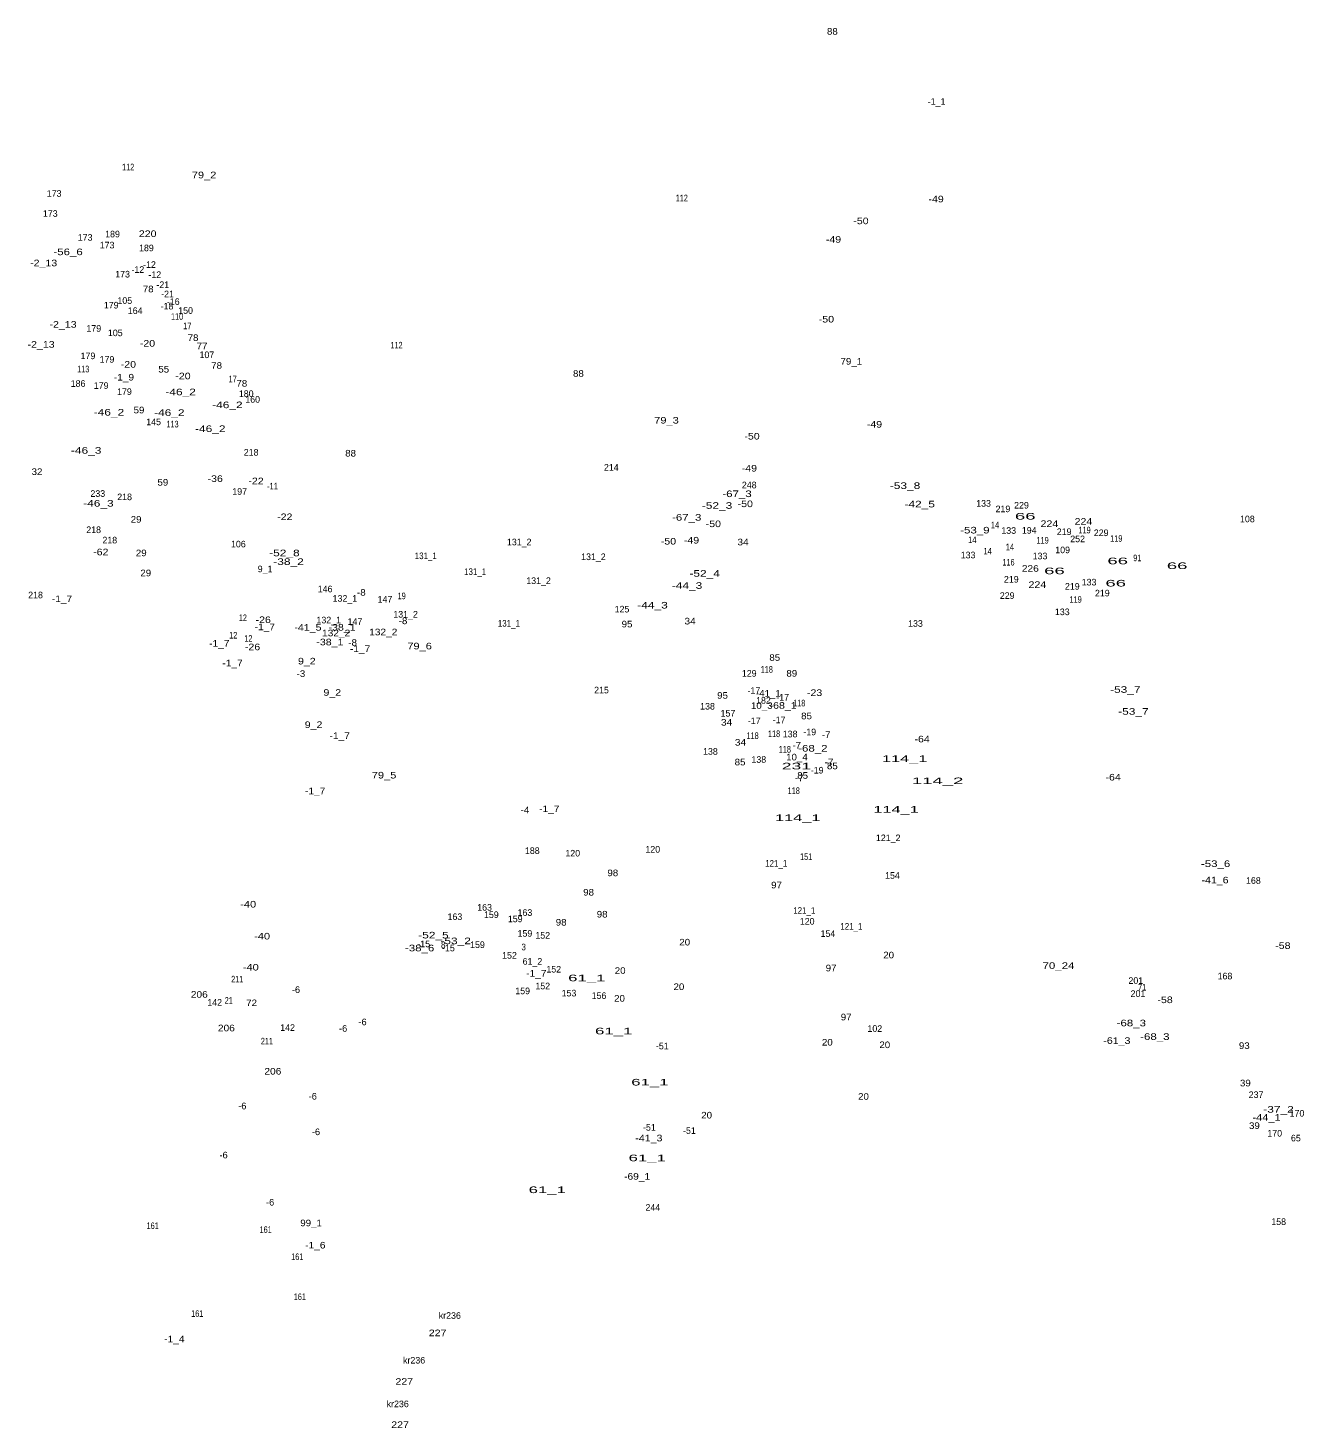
# Model space of a CAD drawing. Extents: x -659306 to -656317, y -989614 to -987663.
# Drawn here: x -657828 to -657055, y -988511 to -987663 of the extents above; entities that cross this region are included whole.
import ezdxf
from ezdxf.enums import TextEntityAlignment as Align

# ---------------------------------------------------------------- set-up
doc = ezdxf.new("R2010")
doc.units = 0
doc.header["$LTSCALE"] = 1.6
doc.layers.add('24', color=7, linetype='Continuous')

msp = doc.modelspace()

# ---------------------------------------------------------------- texts
at = {"layer": '24'}
for s, width, p in [('88', 1.1, (-657340.4, -987667.07)), ('112', 0.8, (-657767.06, -987749.26)), ('79_2', 1.25, (-657721.07, -987754.08)), ('112', 0.8, (-657431.63, -987768.04)), ('-49', 1.2, (-657277.551, -987768.69)), ('-50', 1.2, (-657323.08, -987781.9)), ('220', 1.2, (-657755.25, -987789.69)), ('-49', 1.2, (-657339.731, -987793.14)), ('-56_6', 1.3, (-657803.48, -987800.68)), ('-2_13', 1.2, (-657818.28, -987807.4)), ('78', 1.1, (-657754.94, -987823.18)), ('-2_13', 1.2, (-657806.53, -987844.61)), ('110', 0.8, (-657737.43, -987839.87)), ('-50', 1.2, (-657344.01, -987841.48)), ('17', 0.85, (-657731.221, -987845.54)), ('78', 1.1, (-657727.77, -987852.71)), ('-2_13', 1.2, (-657819.84, -987856.76)), ('-20', 1.2, (-657755.4, -987856.13)), ('77', 1.1, (-657722.341, -987857.75)), ('112', 0.8, (-657604.48, -987857.23)), ('-20', 1.2, (-657766.95, -987868.86)), ('78', 1.1, (-657713.49, -987869.53)), ('79_1', 1.1, (-657328.91, -987867.01)), ('113', 0.8, (-657794.3, -987871.68)), ('-1_9', 1.15, (-657769.671, -987876.65)), ('55', 1.1, (-657745.52, -987871.81)), ('-20', 1.2, (-657733.87, -987875.91)), ('17', 0.85, (-657703.74, -987877.7)), ('88', 1.1, (-657494.27, -987874.4)), ('-46_2', 1.35, (-657735.3, -987885.57)), ('78', 1.1, (-657698.22, -987880.39)), ('-46_2', 1.35, (-657706.95, -987893.4)), ('-46_2', 1.35, (-657778.71, -987897.89)), ('59', 1.1, (-657760.52, -987896.55)), ('-46_2', 1.35, (-657742.14, -987898.09)), ('79_3', 1.25, (-657440.9, -987902.73)), ('113', 0.8, (-657740.22, -987905.08)), ('-46_2', 1.35, (-657717.31, -987907.87)), ('-50', 1.2, (-657389.08, -987912.41)), ('-49', 1.2, (-657314.9, -987905.21)), ('-46_3', 1.35, (-657792.52, -987921)), ('88', 1.1, (-657632.309, -987922.71)), ('32', 1.1, (-657822.319, -987933.91)), ('-36', 1.2, (-657714.35, -987938.11)), ('-49', 1.2, (-657390.681, -987931.82)), ('59', 1.1, (-657746.06, -987940.36)), ('-22', 1.2, (-657689.6, -987939.51)), ('-11', 0.85, (-657679.611, -987942.65)), ('-53_8', 1.35, (-657296.35, -987942.36)), ('-46_3', 1.35, (-657785.09, -987953.08)), ('-52_3', 1.35, (-657410.26, -987954.39)), ('-67_3', 1.3, (-657398.16, -987947.3)), ('-50', 1.2, (-657393.17, -987953.37)), ('-42_5', 1.35, (-657287.49, -987953.56)), ('29', 1.1, (-657762.27, -987962.79)), ('-22', 1.2, (-657672.18, -987961.25)), ('-67_3', 1.3, (-657428.66, -987961.58)), ('66', 2.1, (-657223.541, -987960.92)), ('224', 1.2, (-657188.28, -987964.06)), ('-50', 1.2, (-657412.53, -987965.49)), ('-53_9', 1.3, (-657254.05, -987969.34)), ('14', 0.85, (-657241.829, -987966.23)), ('224', 1.2, (-657208.91, -987965.43)), ('119', 0.8, (-657187.601, -987969.3)), ('-50', 1.2, (-657439.71, -987976.05)), ('-49', 1.2, (-657425.76, -987975.44)), ('34', 1.15, (-657394.52, -987976.55)), ('14', 0.85, (-657255.62, -987975.21)), ('14', 0.85, (-657232.829, -987979.53)), ('119', 0.8, (-657213.02, -987975.46)), ('119', 0.8, (-657168.341, -987974.38)), ('-62', 1.2, (-657783.66, -987982.59)), ('29', 1.1, (-657759.14, -987983.13)), ('-52_8', 1.35, (-657672.4, -987983.15)), ('-38_2', 1.35, (-657669.91, -987988.43)), ('131_1', 0.9, (-657586.75, -987984.9)), ('14', 0.85, (-657246.319, -987982.07)), ('116', 0.8, (-657233.701, -987988.76)), ('66', 2.1, (-657167.511, -987987.99)), ('91', 0.8, (-657155.65, -987986.15)), ('29', 1.1, (-657756.41, -987995.26)), ('131_1', 0.9, (-657556.829, -987994.48)), ('-52_4', 1.35, (-657417.78, -987995.57)), ('226', 1.15, (-657220.47, -987992.55)), ('66', 2.1, (-657205.841, -987994.03)), ('66', 2.1, (-657131.501, -987990.91)), ('-44_3', 1.35, (-657428.44, -988002.89)), ('224', 1.2, (-657216.169, -988002.32)), ('66', 2.1, (-657168.721, -988001.48)), ('-1_7', 1.15, (-657807.13, -988010.94)), ('-8', 1.1, (-657625.79, -988007.06)), ('19', 0.8, (-657601.331, -988009.17)), ('-44_3', 1.35, (-657449.36, -988014.82)), ('119', 0.8, (-657192.981, -988011.35)), ('12', 0.8, (-657697.569, -988022.45)), ('-1_7', 1.15, (-657684.27, -988027.96)), ('-26', 1.2, (-657685.25, -988023.65)), ('-41_5', 1.2, (-657658.15, -988028.25)), ('132_2', 1.15, (-657641.05, -988031.63)), ('-38_1', 1.2, (-657637.47, -988028.22)), ('132_2', 1.15, (-657612.51, -988031.04)), ('-8', 1.1, (-657600.53, -988024.3)), ('131_1', 0.9, (-657536.4, -988025.78)), ('95', 1.1, (-657464.82, -988026.26)), ('34', 1.15, (-657426.59, -988024.47)), ('-1_7', 1.15, (-657711.87, -988037.95)), ('12', 0.8, (-657703.439, -988033.01)), ('12', 0.8, (-657694.25, -988034.97)), ('-26', 1.2, (-657691.71, -988040.1)), ('-38_1', 1.2, (-657644.86, -988037.13)), ('-8', 1.1, (-657631.07, -988037.42)), ('79_6', 1.25, (-657590.51, -988039.59)), ('9_2', 1.2, (-657658.829, -988048.72)), ('-1_7', 1.15, (-657626.56, -988041.2)), ('85', 1.1, (-657375.309, -988046.53)), ('-1_7', 1.15, (-657703.85, -988049.89)), ('-3', 1.1, (-657662.4, -988056.27)), ('118', 0.8, (-657380.13, -988053.71)), ('89', 1.1, (-657364.98, -988056.12)), ('-53_7', 1.35, (-657162.89, -988065.9)), ('9_2', 1.2, (-657643.39, -988067.7)), ('95', 1.1, (-657406.94, -988069.49)), ('-41_1', 1.1, (-657379.189, -988068.22)), ('118', 0.8, (-657360.48, -988074.15)), ('-23', 1.2, (-657351.17, -988067.82)), ('10_3', 1.1, (-657383.18, -988075.66)), ('-68_1', 1.2, (-657370.24, -988075.57)), ('85', 1.1, (-657356.049, -988081.92)), ('-53_7', 1.35, (-657158, -988079.2)), ('9_2', 1.2, (-657654.73, -988087.26)), ('34', 1.15, (-657404.49, -988085.78)), ('-1_7', 1.15, (-657638.89, -988093.88)), ('34', 1.15, (-657396.079, -988097.91)), ('118', 0.8, (-657388.73, -988093.91)), ('118', 0.8, (-657375.73, -988092.74)), ('-7', 1.1, (-657361.99, -988099.69)), ('-7', 1.1, (-657344.171, -988093.22)), ('-64', 1.2, (-657286.01, -988095.96)), ('118', 0.8, (-657369.18, -988102.13)), ('10_4', 1.1, (-657361.87, -988106.86)), ('-68_2', 1.3, (-657352.21, -988101.54)), ('114_1', 1.85, (-657296.597, -988107.78)), ('85', 1.1, (-657396.329, -988109.89)), ('231', 2, (-657362.197, -988112.33)), ('-7', 1.1, (-657342.41, -988109.87)), ('85', 1.1, (-657340.41, -988112.24)), ('79_5', 1.25, (-657612.02, -988117.83)), ('-7', 1.1, (-657360.421, -988119.47)), ('85', 1.1, (-657358.419, -988118)), ('114_2', 2.1, (-657276.621, -988121.26)), ('-64', 1.2, (-657170.26, -988119.04)), ('-1_7', 1.15, (-657653.77, -988127.37)), ('118', 0.8, (-657363.8, -988127.25)), ('-4', 1.15, (-657526.68, -988138.93)), ('-1_7', 1.15, (-657511.92, -988138.22)), ('114_1', 1.85, (-657301.827, -988138.57)), ('114_1', 1.85, (-657361.377, -988143.6)), ('151', 0.8, (-657356.3, -988167.22)), ('121_1', 0.9, (-657374.419, -988171.26)), ('-53_6', 1.3, (-657108.2, -988171.48)), ('98', 1.1, (-657473.44, -988177.04)), ('97', 1.1, (-657374.22, -988184.42)), ('-41_6', 1.2, (-657108.54, -988181.41)), ('98', 1.1, (-657488.11, -988188.78)), ('-40', 1.25, (-657694.35, -988196.03)), ('121_1', 0.9, (-657357.41, -988199.82)), ('98', 1.1, (-657504.73, -988206.97)), ('98', 1.1, (-657479.89, -988202.08)), ('121_1', 0.9, (-657328.86, -988209.4)), ('-40', 1.25, (-657685.93, -988215.41)), ('-52_5', 1.35, (-657582.11, -988214.78)), ('-53_2', 1.35, (-657568.66, -988218.25)), ('-38_6', 1.3, (-657590.46, -988222.58)), ('8', 0.9, (-657576.189, -988220.7)), ('3', 0.9, (-657527.439, -988221.98)), ('20', 1.1, (-657429.86, -988219.03)), ('20', 1.1, (-657306.29, -988226.86)), ('-58', 1.2, (-657067.44, -988221.1)), ('-40', 1.25, (-657692.78, -988234.22)), ('97', 1.1, (-657341.18, -988234.69)), ('70_24', 1.3, (-657203.38, -988233.23)), ('211', 0.8, (-657700.99, -988241.45)), ('-1_7', 1.15, (-657519.75, -988237.9)), ('61_1', 1.9, (-657489.19, -988240.7)), ('20', 1.1, (-657468.97, -988236.25)), ('206', 1.15, (-657723.99, -988250.71)), ('-6', 1.05, (-657665.41, -988247.79)), ('20', 1.1, (-657433.38, -988246.03)), ('71', 0.85, (-657152.691, -988246.33)), ('21', 0.8, (-657706.15, -988254.33)), ('72', 1.1, (-657692.29, -988255.8)), ('20', 1.1, (-657469.36, -988253.07)), ('-58', 1.2, (-657138.81, -988253.96)), ('-6', 1.05, (-657625.09, -988267.38)), ('97', 1.1, (-657332.04, -988264.42)), ('-68_3', 1.3, (-657159.27, -988268.02)), ('206', 1.15, (-657707.571, -988271.05)), ('-6', 1.05, (-657636.83, -988271.29)), ('61_1', 1.9, (-657472.89, -988272.9)), ('-68_3', 1.3, (-657145, -988276.24)), ('211', 0.8, (-657683, -988279.01)), ('20', 1.1, (-657343.439, -988279.67)), ('20', 1.1, (-657308.64, -988281.23)), ('-61_3', 1.2, (-657168.01, -988278.68)), ('93', 1.1, (-657090.8, -988281.74)), ('206', 1.15, (-657679.41, -988297.26)), ('61_1', 1.9, (-657450.96, -988303.89)), ('39', 1.1, (-657090.16, -988304.41)), ('-6', 1.05, (-657697.91, -988318.29)), ('-6', 1.05, (-657655.23, -988312.42)), ('20', 1.1, (-657321.54, -988312.53)), ('-37_2', 1.35, (-657070.07, -988320.36)), ('20', 1.1, (-657416.569, -988323.88)), ('-44_1', 1.25, (-657077.3, -988325.24)), ('-6', 1.05, (-657653.28, -988333.96)), ('39', 1.1, (-657084.68, -988330.23)), ('-41_3', 1.2, (-657451.559, -988337.74)), ('-6', 1.05, (-657709.26, -988348.06)), ('61_1', 1.9, (-657452.57, -988349.78)), ('-69_1', 1.15, (-657458.7, -988360.98)), ('61_1', 1.9, (-657513.13, -988369.1)), ('-6', 1.05, (-657681.07, -988376.65)), ('161', 0.8, (-657752.221, -988390.89)), ('161', 0.8, (-657683.78, -988393.24)), ('99_1', 1.1, (-657656.24, -988389.18)), ('-1_6', 1.15, (-657653.671, -988402.67)), ('161', 0.8, (-657664.62, -988409.67)), ('161', 0.8, (-657663.061, -988433.93)), ('161', 0.8, (-657725.231, -988444.1)), ('227', 1.2, (-657579.57, -988455.81)), ('-1_4', 1.15, (-657739.069, -988459.52)), ('227', 1.2, (-657599.78, -988485.28)), ('227', 1.2, (-657602.32, -988511.46))]:
    msp.add_text(s, height=4, dxfattribs=dict(at, width=width)).set_placement(p, align=Align.CENTER)
for s, p in [('-1_1', (-657277.25, -987709.56)), ('173', (-657811.91, -987765.3)), ('173', (-657814.26, -987777.43)), ('173', (-657793.14, -987791.9)), ('189', (-657776.551, -987789.88)), ('173', (-657779.851, -987796.59)), ('189', (-657756.02, -987798.29)), ('-12', (-657761.211, -987811.39)), ('-12', (-657754.171, -987808.36)), ('173', (-657770.461, -987814.2)), ('-12', (-657750.941, -987814.53)), ('-21', (-657746.101, -987820.61)), ('-21', (-657743.221, -987826.19)), ('179', (-657777.35, -987832.99)), ('105', (-657769.12, -987830.21)), ('164', (-657762.84, -987836.32)), ('-18', (-657743.53, -987833.57)), ('-16', (-657739.76, -987830.83)), ('150', (-657732.28, -987836.23)), ('179', (-657787.91, -987847.08)), ('105', (-657774.89, -987849.77)), ('179', (-657791.43, -987863.7)), ('179', (-657779.9, -987865.85)), ('107', (-657719.38, -987863.06)), ('186', (-657797.431, -987880.48)), ('179', (-657783.42, -987881.7)), ('179', (-657769.34, -987885.41)), ('180', (-657695.54, -987886.61)), ('160', (-657691.65, -987890.09)), ('145', (-657751.65, -987903.71)), ('218', (-657692.579, -987922.17)), ('214', (-657474.34, -987931.29)), ('233', (-657785.477, -987947.14)), ('197', (-657699.52, -987945.9)), ('248', (-657390.771, -987941.97)), ('218', (-657769.23, -987949.16)), ('133', (-657248.79, -987953.12)), ('229', (-657225.813, -987954.23)), ('219', (-657237.061, -987956.45)), ('108', (-657088.94, -987962.53)), ('218', (-657788, -987969.11)), ('133', (-657233.54, -987969.55)), ('194', (-657221.13, -987969.43)), ('219', (-657199.961, -987970.3)), ('229', (-657177.533, -987970.94)), ('218', (-657778.22, -987975.37)), ('106', (-657700.311, -987977.78)), ('131_2', (-657530.14, -987976.49)), ('252', (-657191.807, -987974.63)), ('131_2', (-657485.17, -987985.48)), ('133', (-657258.179, -987984.42)), ('133', (-657214.579, -987985)), ('109', (-657200.88, -987981.3)), ('9_1', (-657684.11, -987992.83)), ('146', (-657647.75, -988004.97)), ('131_2', (-657518.41, -987999.96)), ('219', (-657231.981, -987999.09)), ('219', (-657195.02, -988003.39)), ('133', (-657184.86, -988000.85)), ('218', (-657823.189, -988008.62)), ('132_1', (-657635.77, -988010.7)), ('147', (-657611.48, -988011.23)), ('229', (-657234.463, -988008.98)), ('219', (-657176.841, -988007.5)), ('131_2', (-657598.97, -988020.3)), ('125', (-657467.86, -988017.21)), ('133', (-657201.079, -988018.84)), ('132_1', (-657645.55, -988023.8)), ('147', (-657629.66, -988024.72)), ('133', (-657290.049, -988025.89)), ('129', (-657390.76, -988056.11)), ('215', (-657480.28, -988066.26)), ('-17', (-657387.93, -988066.49)), ('182', (-657382.16, -988072.53)), ('-17', (-657370.5, -988070.6)), ('138', (-657416.049, -988076.05)), ('157', (-657403.671, -988080.3)), ('-17', (-657387.73, -988084.9)), ('-17', (-657372.66, -988084.31)), ('138', (-657365.99, -988092.87)), ('-19', (-657354.11, -988091.61)), ('138', (-657414.29, -988103.43)), ('138', (-657384.959, -988108.32)), ('-19', (-657349.6, -988114.81)), ('121_2', (-657306.57, -988155.81)), ('188', (-657522.199, -988163.57)), ('120', (-657497.71, -988165.11)), ('120', (-657449.22, -988162.76)), ('154', (-657304, -988178.6)), ('168', (-657085.301, -988181.66)), ('163', (-657551.13, -988197.95)), ('163', (-657526.691, -988201.08)), ('163', (-657569.12, -988203.62)), ('159', (-657547.02, -988202.39)), ('159', (-657532.551, -988204.93)), ('120', (-657355.65, -988206.38)), ('159', (-657526.681, -988213.73)), ('152', (-657515.88, -988214.89)), ('154', (-657343.1, -988213.81)), ('-15', (-657588.01, -988220.08)), ('-15', (-657573.041, -988222.53)), ('159', (-657555.431, -988220.58)), ('152', (-657536.02, -988227.01)), ('61_2', (-657522.124, -988230.68)), ('152', (-657509.23, -988235.43)), ('201', (-657156.54, -988242.3)), ('168', (-657102.51, -988239.56)), ('159', (-657528.051, -988248.55)), ('152', (-657515.88, -988245.6)), ('153', (-657499.98, -988249.92)), ('156', (-657481.77, -988251.44)), ('201', (-657155.22, -988250.22)), ('142', (-657714.669, -988255.54)), ('142', (-657670.49, -988270.79)), ('102', (-657314.68, -988271.38)), ('-51', (-657443.451, -988281.96)), ('237', (-657083.693, -988311.47)), ('170', (-657058.89, -988322.72)), ('-51', (-657451.27, -988331.25)), ('-51', (-657427.02, -988333.21)), ('170', (-657072.38, -988334.85)), ('65', (-657059.573, -988337.77)), ('244', (-657449.186, -988379.8)), ('158', (-657069.97, -988388.42)), ('kr236', (-657572.174, -988445.3)), ('kr236', (-657593.814, -988472.39)), ('kr236', (-657603.754, -988498.85))]:
    msp.add_text(s, height=4, dxfattribs=at).set_placement(p, align=Align.CENTER)

doc.saveas('drawing.dxf')
